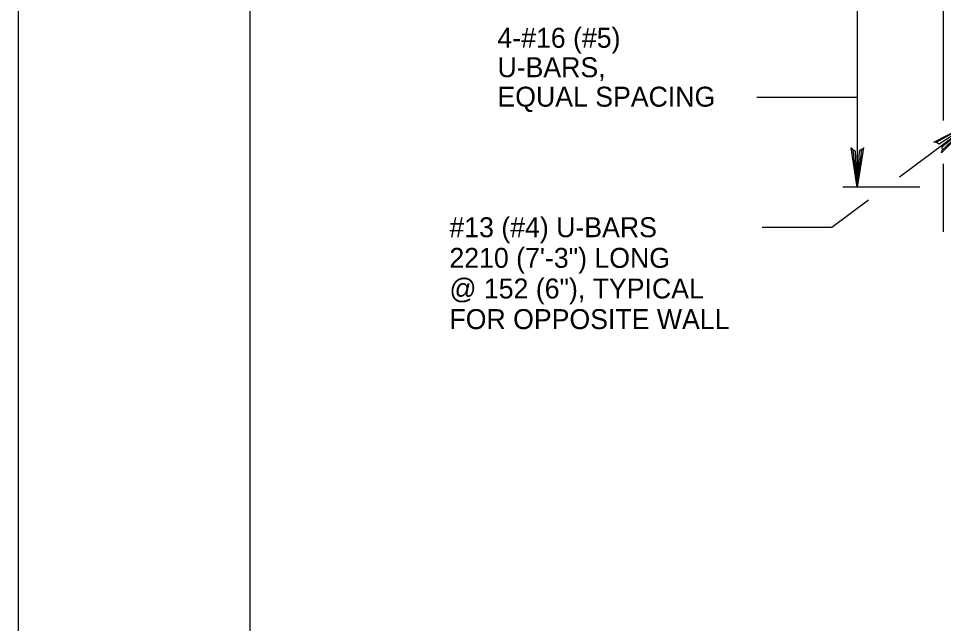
# Model space of a CAD drawing. Extents: x 638455 to 640199, y 298558 to 299152.
# Drawn here: x 638454.6 to 638610.5, y 298858.8 to 298960.7 of the extents above; entities that cross this region are included whole.
import ezdxf

# ---------------------------------------------------------------- set-up
doc = ezdxf.new("R2010")
doc.units = 0
for name, color, linetype in [('1', 7, 'Continuous'), ('2', 7, 'Continuous'), ('3', 7, 'Continuous'), ('PLT-BNDY', 7, 'Continuous')]:
    doc.layers.add(name, color=color, linetype=linetype)

msp = doc.modelspace()

# ---------------------------------------------------------------- linework, layer by layer
at = {"layer": '1'}
for points in [[(639279.61, 298573.25), (639279.61, 299137.25), (638493.61, 299137.25), (638493.61, 298573.25), (639279.61, 298573.25), (639279.61, 298599.61), (639079.61, 298599.61), (639079.61, 298664.29), (639279.61, 298664.29), (639279.61, 298693.25), (639079.61, 298693.25), (639079.61, 298573.25), (639158.42, 298573.25), (639158.42, 298599.61), (639158.42, 298573.25), (639235.42, 298573.25), (639235.42, 298599.61), (639235.42, 298587.29), (639279.61, 298587.29)], [(638609.27, 298939.89), (638609.76, 298939.65), (638615.18, 298943.15), (638609.27, 298939.89), (638608.82, 298939.93), (638615.18, 298943.15), (638610.16, 298939.1), (638610.25, 298938.58), (638615.18, 298943.15), (638610.15, 298938.1), (638610.25, 298938.58)]]:
    msp.add_lwpolyline(points, dxfattribs=at)
at = {"layer": '2'}
for p, q in [((638595.94, 299046), (638595.94, 298932.33)), ((638610.47, 298943.57), (638610.47, 299045.2)), ((638578.99, 298947.51), (638595.94, 298947.51)), ((638603.05, 298934.09), (638615.18, 298943.15)), ((638610.47, 298924.83), (638610.47, 298936.28)), ((638606.5, 298932.33), (638593.5, 298932.33)), ((638591.64, 298925.58), (638597.83, 298930.2)), ((638579.93, 298925.58), (638591.64, 298925.58))]:
    msp.add_line(p, q, dxfattribs=at)
msp.add_lwpolyline([(638596.73, 298938.66), (638596.27, 298938.42), (638595.94, 298932.33), (638596.73, 298938.66), (638597.01, 298938.98), (638595.94, 298932.33), (638595.64, 298938.42), (638595.18, 298938.64), (638595.94, 298932.33), (638594.88, 298938.98), (638595.18, 298938.64)], dxfattribs=at)
at = {"layer": 'PLT-BNDY'}
msp.add_lwpolyline([(638454.61, 299152.25), (639295.61, 299152.25), (639295.61, 298558.25), (638454.61, 298558.25)], close=True, dxfattribs=at)

# ---------------------------------------------------------------- texts
at = {"layer": '3'}
for s, p in [('4-#16 (#5)', (638535.31, 298955.82)), ('U-BARS,', (638535.31, 298950.86)), ('EQUAL SPACING', (638535.31, 298945.9)), ('#13 (#4) U-BARS', (638527.22, 298923.91)), ('2210 (7\'-3") LONG', (638527.22, 298918.75)), ('@ 152 (6"), TYPICAL', (638527.22, 298913.59)), ('FOR OPPOSITE WALL', (638527.22, 298908.43))]:
    msp.add_text(s, height=3.36, dxfattribs=at).set_placement(p)

doc.saveas('drawing.dxf')
